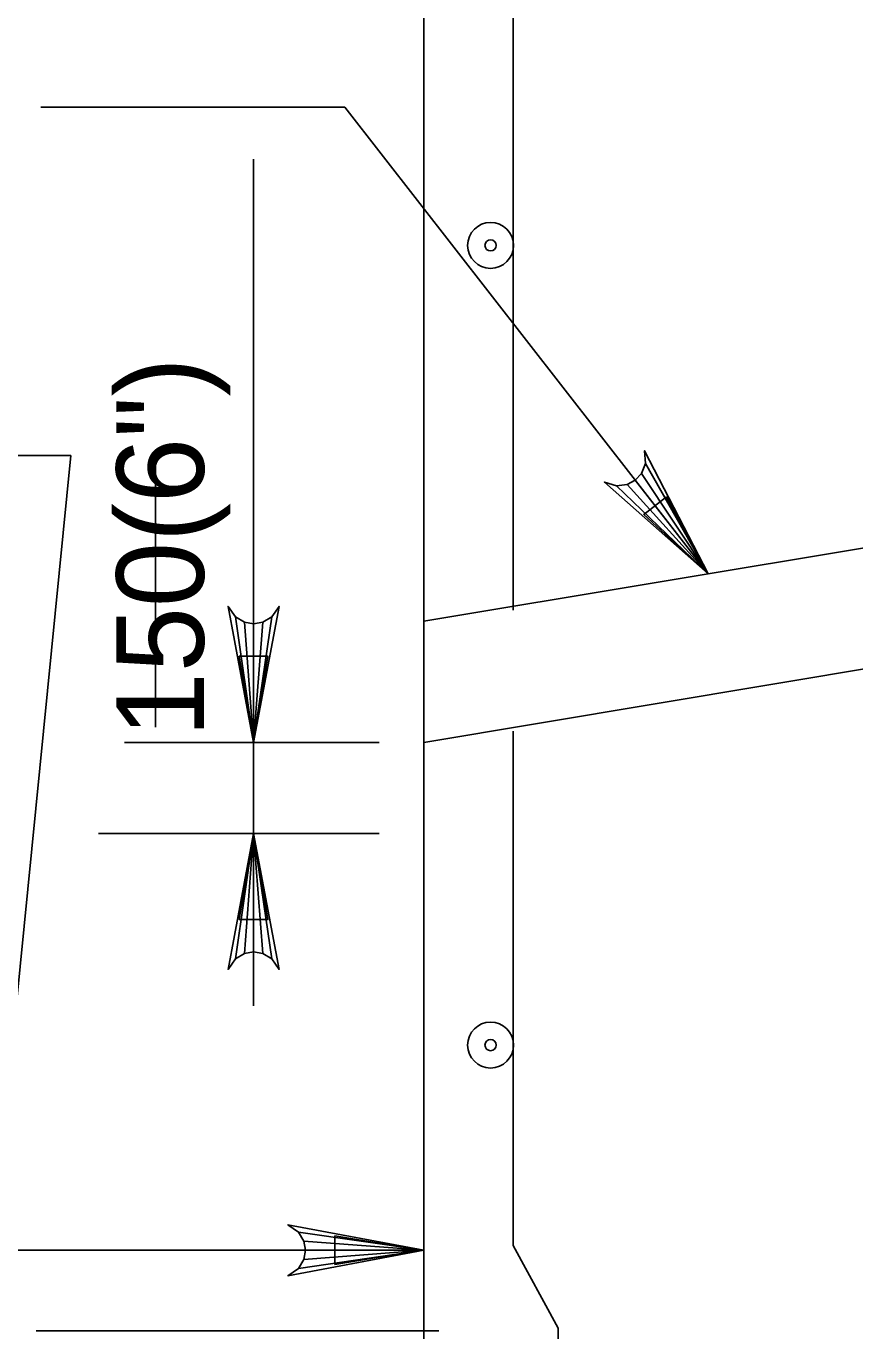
# Model space of a CAD drawing. Extents: x 179 to 454, y -271 to 54.
# Drawn here: x 270.997 to 272.134, y -50.775 to -48.986 of the extents above; entities that cross this region are included whole.
import ezdxf

# ---------------------------------------------------------------- set-up
doc = ezdxf.new("R2010")
doc.units = 0
for name, color, linetype in [('Level 3', 7, 'Continuous'), ('Level 4', 7, 'Continuous'), ('Level 41', 7, 'Continuous'), ('Level 5', 7, 'Continuous'), ('Level 6', 7, 'Continuous'), ('Level 9', 7, 'Continuous')]:
    doc.layers.add(name, color=color, linetype=linetype)

# ---------------------------------------------------------------- blocks, each defined once
blk = doc.blocks.new('B')
at = {"layer": 'Level 3'}
blk.add_circle((0, 0), 0.1066, dxfattribs=at)
for start, end in [(0, 180), (180, 0)]:
    blk.add_arc((0, 0), 0.026, start, end, dxfattribs=at)

msp = doc.modelspace()

# ---------------------------------------------------------------- linework, layer by layer
at = {"layer": 'Level 3'}
for p, q in [((271.4345, -49.0972), (271.0175, -49.0972)), ((271.9325, -49.737), (271.4345, -49.0972))]:
    msp.add_line(p, q, dxfattribs=at)
msp.add_lwpolyline([(271.8755, -49.6317), (271.8444, -49.6559), (271.9325, -49.737)], close=True, dxfattribs=at)
at = {"layer": 'Level 4'}
for p, q in [((271.3093, -49.732), (271.3093, -49.1686)), ((269.2521, -49.575), (271.0588, -49.575)), ((271.0588, -49.575), (270.9504, -50.6645)), ((271.3093, -49.8501), (271.3093, -49.732)), ((271.4813, -49.9682), (271.1322, -49.9682)), ((271.3093, -50.093), (271.3093, -49.9682)), ((271.4813, -50.093), (271.0968, -50.093)), ((271.2805, -50.093), (271.1322, -50.093)), ((271.3093, -50.2111), (271.3093, -50.3293)), ((270.307, -50.6645), (271.5428, -50.6645)), ((271.5633, -50.7751), (271.011, -50.7751))]:
    msp.add_line(p, q, dxfattribs=at)
for points in [[(271.9325, -49.737), (271.7904, -49.6113), (271.8071, -49.6166), (271.8215, -49.6148), (271.8327, -49.6088), (271.8413, -49.5994), (271.8466, -49.5858), (271.8456, -49.5684), (271.9325, -49.737), (271.8466, -49.5858), (271.8413, -49.5994), (271.9325, -49.737), (271.8327, -49.6088), (271.8215, -49.6148), (271.9325, -49.737), (271.8071, -49.6166)], [(271.3093, -49.9682), (271.2744, -49.7817), (271.2843, -49.7961), (271.2968, -49.8035), (271.3093, -49.8057), (271.3218, -49.8035), (271.3343, -49.7961), (271.3442, -49.7817), (271.3093, -49.9682), (271.3343, -49.7961), (271.3218, -49.8035), (271.3093, -49.9682), (271.3093, -49.8057), (271.2968, -49.8035), (271.3093, -49.9682), (271.2843, -49.7961)], [(271.3093, -50.093), (271.3442, -50.2794), (271.3343, -50.2651), (271.3218, -50.2577), (271.3093, -50.2555), (271.2968, -50.2577), (271.2843, -50.2651), (271.2744, -50.2794), (271.3093, -50.093), (271.2843, -50.2651), (271.2968, -50.2577), (271.3093, -50.093), (271.3093, -50.2555), (271.3218, -50.2577), (271.3093, -50.093), (271.3343, -50.2651)], [(271.5428, -50.6645), (271.3564, -50.6994), (271.3707, -50.6895), (271.3782, -50.677), (271.3803, -50.6645), (271.3782, -50.652), (271.3707, -50.6395), (271.3564, -50.6296), (271.5428, -50.6645), (271.3707, -50.6395), (271.3782, -50.652), (271.5428, -50.6645), (271.3803, -50.6645), (271.3782, -50.677), (271.5428, -50.6645), (271.3707, -50.6895)]]:
    msp.add_lwpolyline(points, dxfattribs=at)
for points in [[(271.2897, -49.8501), (271.329, -49.8501), (271.3093, -49.9682)], [(271.2897, -50.2111), (271.329, -50.2111), (271.3093, -50.093)], [(271.4209, -50.6842), (271.4209, -50.6448), (271.5391, -50.6645)]]:
    msp.add_lwpolyline(points, close=True, dxfattribs=at)
at = {"layer": 'Level 41'}
msp.add_line((271.1748, -49.9471), (271.1748, -49.5879), dxfattribs=at)
at = {"layer": 'Level 5'}
msp.add_line((271.5391, -50.6645), (271.5391, -50.6645), dxfattribs=at)
at = {"layer": 'Level 6'}
for p, q in [((271.6654, -49.7867), (271.6654, -46.8203)), ((271.6654, -50.6579), (271.6654, -49.9529)), ((271.7269, -50.7715), (271.6654, -50.6579)), ((271.7269, -51.5389), (271.7269, -50.7715))]:
    msp.add_line(p, q, dxfattribs=at)
at = {"layer": 'Level 9'}
for p, q in [((271.5428, -51.5902), (271.5428, -46.1403)), ((272.5744, -49.63), (271.5428, -49.8019)), ((273.2674, -49.6807), (271.5428, -49.9682)), ((271.5428, -50.1457), (271.5428, -50.1512))]:
    msp.add_line(p, q, dxfattribs=at)

# ---------------------------------------------------------------- block references
at = {"layer": 'Level 3', "xscale": 0.29527500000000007, "yscale": 0.29527500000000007, "rotation": 90}
for p in [(271.6343, -49.2868), (271.6343, -50.3832)]:
    msp.add_blockref('B', p, dxfattribs=at)

# ---------------------------------------------------------------- texts
at = {"layer": 'Level 3'}
msp.add_text('150(6")', height=0.12, rotation=90, dxfattribs=at).set_placement((271.2411, -49.9612))

doc.saveas('drawing.dxf')
